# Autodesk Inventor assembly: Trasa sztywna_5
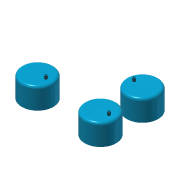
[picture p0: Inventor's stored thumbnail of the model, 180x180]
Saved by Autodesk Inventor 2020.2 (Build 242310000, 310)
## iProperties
Created: 2014-08
Part Number: Trasa sztywna_5
Document SubType Name: Assembly
Designer: F.Stasiak
Catalog Web Link: www.expertbooks.pl
Manager: www.cadconsulting.pl
Company: Fabian Stasiak CAD Consulting
Author: F.Stasiak
Subject: Zbiór ćwiczeń. Autodesk Inventor 2020. Kurs Professional
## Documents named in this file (2)
- C:\2020_Kurs_Professional\R1 Rury\Trasa sztywna_5.iam
- C:\2020_Kurs_Professional\R1 Rury\Konstrukcja_5.ipt
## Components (3 placed, 1 different names)
1. Konstrukcja_5:1 — Równoległy:1, Równoległy:2, Równoległy:3, Zestawiający:5, Równoległy:5, Zestawiający:6
2. Konstrukcja_5:2 — Równoległy:1, Równoległy:2, Równoległy:3
3. Konstrukcja_5:3 — Zestawiający:5, Równoległy:5, Zestawiający:6
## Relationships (6: Flush 4, Mate 2)
- Równoległy:1 [Flush]: Konstrukcja_5:1 ↔ Konstrukcja_5:2
- Równoległy:2 [Flush]: Konstrukcja_5:1 ↔ Konstrukcja_5:2
- Równoległy:3 [Flush]: Konstrukcja_5:1 ↔ Konstrukcja_5:2
- Zestawiający:5 [Mate]: Konstrukcja_5:1 ↔ Konstrukcja_5:3
- Równoległy:5 [Flush]: Konstrukcja_5:1 ↔ Konstrukcja_5:3
- Zestawiający:6 [Mate]: Konstrukcja_5:1 ↔ Konstrukcja_5:3
